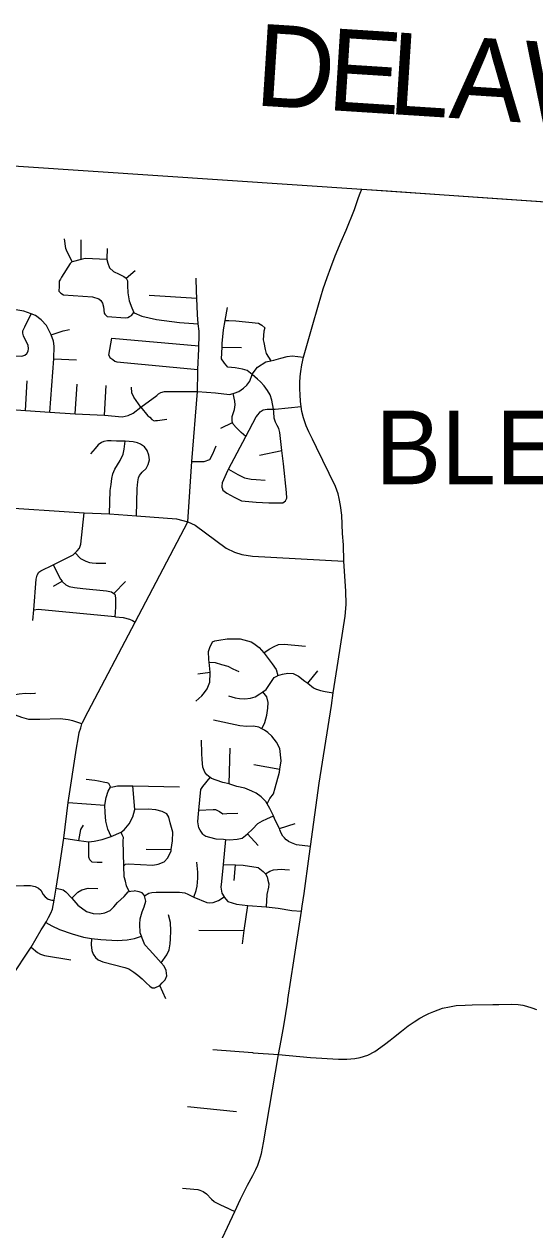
# Model space of a CAD drawing. Extents: x 1755200 to 1902939, y 644115 to 788070.
# Drawn here: x 1856712 to 1862951, y 763803 to 778525 of the extents above; entities that cross this region are included whole.
import ezdxf

# ---------------------------------------------------------------- set-up
doc = ezdxf.new("R2010")
doc.units = 0
for name, color, linetype in [('GM_X_Adjacent_County_Text', 7, 'Continuous'), ('GM_X_City_Street', 7, 'Continuous'), ('GM_X_County', 7, 'Continuous'), ('GM_X_County_Road', 7, 'Continuous'), ('GM_X_Township_Text', 7, 'Continuous')]:
    doc.layers.add(name, color=color, linetype=linetype)

msp = doc.modelspace()

# ---------------------------------------------------------------- linework, layer by layer
at = {"layer": 'GM_X_City_Street'}
for points in [[(1851193, 777116), (1851228, 777114), (1853977, 776957), (1854746, 776908), (1855849, 776844), (1860837, 776510)], [(1860818, 776461), (1860837, 776510)], [(1860837, 776510), (1861151, 776489)], [(1860586, 775869), (1860647, 776011), (1860746, 776261), (1860798, 776408), (1860818, 776461)], [(1857298, 775622), (1857229, 775764), (1857221, 775784), (1857207, 775903)], [(1857407, 775651), (1857408, 775893)], [(1857727, 775786), (1857721, 775660), (1857724, 775649), (1857736, 775608), (1857754, 775551), (1857803, 775506), (1857872, 775472), (1857929, 775444), (1857960, 775422), (1857973, 775391), (1857976, 775333), (1857977, 775243), (1857996, 775146), (1858028, 775061), (1858054, 775005), (1858058, 774998), (1858151, 774958), (1858331, 774917), (1858612, 774883), (1858840, 774864)], [(1860109, 767756), (1860133, 767908), (1860195, 768367), (1860210, 768482), (1860314, 769257), (1860465, 770206), (1860488, 770360), (1860547, 770745), (1860633, 771296), (1860638, 771339), (1860645, 771441), (1860641, 771603), (1860619, 771968), (1860612, 772166), (1860602, 772305), (1860591, 772531), (1860578, 772649), (1860562, 772731), (1860547, 772789), (1860515, 772880), (1860282, 773356), (1860233, 773457), (1860188, 773548), (1860159, 773620), (1860123, 773719), (1860103, 773796), (1860096, 773856), (1860089, 773919), (1860083, 774004), (1860080, 774068), (1860080, 774146), (1860084, 774222), (1860091, 774284), (1860106, 774366), (1860125, 774459), (1860230, 774829), (1860307, 775098), (1860364, 775294), (1860413, 775431), (1860457, 775554), (1860512, 775695), (1860586, 775869)], [(1857724, 775649), (1857456, 775664), (1857407, 775651), (1857298, 775622), (1857291, 775620), (1857274, 775601), (1857169, 775437), (1857155, 775410), (1857142, 775386), (1857140, 775320), (1857137, 775266), (1857162, 775239), (1857195, 775220), (1857548, 775195), (1857625, 775170), (1857651, 775150), (1857670, 775119), (1857681, 775075), (1857688, 774994), (1857698, 774984), (1857725, 774957), (1857952, 774937), (1857980, 774942), (1858001, 774954), (1858023, 774967), (1858054, 775005)], [(1857960, 775422), (1858067, 775517)], [(1857028, 773787), (1857074, 774437), (1857079, 774594), (1857071, 774655), (1857042, 774730), (1856987, 774846), (1856919, 774916), (1856851, 774967), (1856800, 774989), (1856708, 775020), (1856611, 775037), (1856360, 775047), (1856260, 775066), (1856193, 775100), (1856147, 775134), (1856103, 775185), (1856062, 775243), (1856028, 775301), (1855972, 775345), (1855924, 775367), (1855856, 775388), (1855762, 775403)], [(1858829, 774041), (1858834, 774276), (1858836, 774306), (1858845, 774560), (1858846, 774598), (1858851, 774706), (1858851, 774778), (1858840, 774864), (1858839, 774868), (1858828, 774977), (1858824, 775085), (1858822, 775171), (1858822, 775177), (1858819, 775266), (1858813, 775422)], [(1858238, 775216), (1858822, 775177)], [(1856147, 775134), (1856074, 775049), (1856060, 775012), (1856050, 774963), (1856032, 774679), (1856038, 774640), (1856054, 774605), (1856082, 774581), (1856138, 774549), (1856211, 774520), (1856307, 774497), (1856413, 774488), (1856605, 774476), (1856685, 774470), (1856721, 774482), (1856747, 774503), (1856763, 774531), (1856767, 774563), (1856762, 774602), (1856703, 774718), (1856695, 774751), (1856697, 774781), (1856720, 774827), (1856800, 774989)], [(1859497, 774248), (1859436, 774295), (1859379, 774313), (1859291, 774329), (1859200, 774338), (1859161, 774387), (1859123, 774440), (1859130, 774582), (1859132, 774624), (1859147, 774792), (1859168, 774907), (1859197, 775065)], [(1859168, 774907), (1859212, 774906), (1859300, 774904), (1859573, 774874), (1859614, 774849), (1859653, 774818), (1859642, 774778), (1859631, 774670), (1859642, 774636), (1859657, 774553), (1859670, 774503), (1859724, 774414)], [(1857042, 774730), (1857189, 774782), (1857267, 774796)], [(1857748, 774484), (1857785, 774691), (1858846, 774598)], [(1859130, 774582), (1859366, 774575)], [(1856507, 773824), (1856728, 773807), (1857028, 773787), (1857335, 773766), (1857694, 773749), (1857911, 773728), (1857984, 773747), (1858045, 773774), (1858139, 773846), (1858332, 773992), (1858353, 774012), (1858383, 774027), (1858427, 774038), (1858521, 774038), (1858829, 774041), (1859048, 774022), (1859221, 774004), (1859267, 774015), (1859277, 774017), (1859334, 774040), (1859390, 774080), (1859433, 774118), (1859468, 774165), (1859497, 774248), (1859498, 774252), (1859562, 774337), (1859666, 774401), (1859724, 774414), (1859764, 774423), (1859848, 774445), (1859927, 774465), (1859987, 774474), (1860125, 774459)], [(1857074, 774437), (1857350, 774427)], [(1857748, 774484), (1857759, 774456), (1857794, 774431), (1857821, 774410), (1857845, 774403), (1858836, 774306)], [(1856728, 773807), (1856749, 774169)], [(1857335, 773766), (1857359, 774129)], [(1859904, 772706), (1859921, 772736), (1859918, 772806), (1859882, 773158), (1859862, 773317), (1859835, 773537), (1859824, 773586), (1859802, 773626), (1859783, 773663), (1859768, 773713), (1859764, 773793), (1859758, 773825), (1859737, 773932), (1859717, 773997), (1859686, 774050), (1859645, 774107), (1859600, 774158), (1859563, 774191), (1859497, 774248)], [(1857694, 773749), (1857713, 774113)], [(1858139, 773846), (1858052, 773970), (1858028, 774025), (1858023, 774091)], [(1858712, 772446), (1858760, 773186), (1858829, 774041)], [(1859420, 773489), (1859365, 773540), (1859308, 773595), (1859267, 773640), (1859259, 773661), (1859252, 773681), (1859255, 773735), (1859283, 773818), (1859290, 773876), (1859287, 773921), (1859267, 774015)], [(1858139, 773846), (1858225, 773742), (1858248, 773724), (1858274, 773699), (1858299, 773681), (1858318, 773684), (1858340, 773684), (1858454, 773703)], [(1859130, 772862), (1859130, 772894), (1859137, 772912), (1859135, 772930), (1859202, 773075), (1859210, 773089), (1859420, 773489), (1859547, 773730), (1859569, 773760), (1859594, 773789), (1859631, 773815), (1859681, 773825), (1859758, 773825), (1859777, 773825), (1860096, 773856)], [(1859116, 773592), (1859259, 773661)], [(1858083, 772520), (1858093, 772856), (1858103, 772938), (1858111, 772987), (1858121, 773014), (1858154, 773053), (1858204, 773100), (1858228, 773149), (1858244, 773206), (1858236, 773261), (1858217, 773320), (1858182, 773364), (1858135, 773398), (1858097, 773413), (1858046, 773426), (1857946, 773431), (1857839, 773431), (1857777, 773435), (1857729, 773436), (1857687, 773428), (1857656, 773416), (1857618, 773389), (1857581, 773345), (1857521, 773278)], [(1857753, 772545), (1857765, 772829), (1857774, 772905), (1857783, 772977), (1857797, 773033), (1857821, 773092), (1857884, 773196), (1857922, 773274), (1857935, 773335), (1857946, 773431)], [(1858760, 773186), (1858911, 773183), (1858982, 773209), (1859019, 773280), (1859056, 773374)], [(1859588, 773263), (1859862, 773317)], [(1859210, 773089), (1859321, 773026), (1859406, 772984), (1859484, 772968), (1859548, 772963), (1859656, 772956)], [(1859130, 772862), (1859139, 772834), (1859190, 772797), (1859279, 772749), (1859366, 772705), (1859546, 772688), (1859700, 772679), (1859820, 772680), (1859872, 772679), (1859904, 772706)], [(1855772, 772483), (1856143, 772622), (1856193, 772633), (1856234, 772636), (1856339, 772631), (1857445, 772557), (1857753, 772545), (1858083, 772520), (1858575, 772486), (1858649, 772466), (1858712, 772446), (1858803, 772406), (1859181, 772127), (1859281, 772079), (1859372, 772050), (1859503, 772030), (1860619, 771968)], [(1856820, 771244), (1856830, 771374), (1856858, 771748), (1856873, 771796), (1856893, 771832), (1856915, 771848), (1857067, 771924), (1857310, 772047), (1857337, 772068), (1857360, 772093), (1857387, 772126), (1857403, 772174), (1857445, 772557)], [(1856549, 766881), (1856798, 767255), (1856921, 767465), (1856954, 767517), (1856979, 767556), (1856986, 767567), (1857010, 767617), (1857039, 767669), (1857057, 767719), (1857078, 767829), (1857103, 767973), (1857141, 768207), (1857198, 768584), (1857249, 769022), (1857351, 769683), (1857372, 769799), (1857386, 769877), (1857403, 769931), (1857419, 769983), (1857427, 769997), (1857496, 770133), (1858068, 771223), (1858712, 772446)], [(1857337, 772068), (1857402, 772002), (1857464, 771967), (1857511, 771951), (1857543, 771949), (1857591, 771942), (1857711, 771943)], [(1857067, 771924), (1857155, 771749), (1857176, 771722), (1857182, 771714), (1857223, 771677), (1857261, 771659), (1857327, 771647), (1857428, 771633), (1857720, 771606), (1857778, 771593), (1857807, 771574), (1857819, 771566), (1857828, 771519), (1857830, 771425), (1857824, 771327), (1857819, 771305), (1857819, 771291)], [(1857071, 771663), (1857176, 771722)], [(1857807, 771574), (1857952, 771719)], [(1856830, 771374), (1856884, 771381), (1857097, 771361), (1857819, 771291), (1857830, 771289), (1857922, 771278), (1857998, 771261), (1858036, 771243), (1858068, 771223)], [(1858808, 770257), (1858881, 770324), (1858917, 770364), (1858950, 770408), (1858981, 770492), (1858984, 770602), (1858983, 770613), (1858971, 770736), (1858968, 770768), (1858963, 770864), (1858980, 770912), (1859015, 770984)], [(1859015, 770984), (1859041, 770994), (1859089, 771005), (1859191, 771020), (1859353, 771018), (1859487, 770982), (1859518, 770964), (1859582, 770915), (1859640, 770849), (1859643, 770846), (1859741, 770716), (1859791, 770646), (1859813, 770571)], [(1859640, 770849), (1859706, 770895), (1859768, 770924), (1859818, 770950), (1859888, 770955), (1860150, 770928)], [(1858971, 770736), (1859046, 770731), (1859125, 770704), (1859199, 770685), (1859261, 770654), (1859334, 770619)], [(1858832, 770590), (1858983, 770613)], [(1859209, 770322), (1859288, 770297), (1859344, 770289), (1859408, 770288), (1859476, 770295), (1859533, 770312), (1859593, 770346), (1859628, 770371), (1859670, 770401), (1859716, 770474), (1859767, 770548), (1859808, 770569), (1859813, 770571), (1859868, 770587), (1859934, 770600), (1859998, 770596), (1860062, 770564), (1860140, 770504), (1860177, 770476), (1860245, 770422), (1860279, 770404), (1860283, 770403)], [(1860177, 770476), (1860299, 770629)], [(1857419, 769983), (1857309, 770018), (1857251, 770032), (1857151, 770042), (1856903, 770035), (1856771, 770034), (1856685, 770059), (1856606, 770086), (1856548, 770111), (1856518, 770156), (1856476, 770198), (1856447, 770247), (1856426, 770319), (1856417, 770395), (1856427, 770499)], [(1856426, 770319), (1856497, 770346), (1856579, 770337), (1856653, 770348), (1856727, 770355), (1856791, 770353), (1856845, 770356), (1856851, 770356)], [(1859615, 769922), (1859651, 769998), (1859676, 770086), (1859687, 770172), (1859694, 770240), (1859675, 770312), (1859628, 770371)], [(1860283, 770403), (1860333, 770388), (1860388, 770377), (1860488, 770360)], [(1859680, 769006), (1859714, 769069), (1859760, 769127), (1859779, 769201), (1859832, 769393), (1859837, 769429), (1859853, 769531), (1859834, 769680), (1859796, 769758), (1859737, 769829), (1859687, 769875), (1859647, 769906), (1859615, 769922), (1859578, 769940), (1859512, 769951), (1859432, 769948), (1859348, 769956), (1859026, 770025)], [(1859913, 768567), (1859892, 768588), (1859874, 768610), (1859851, 768647), (1859834, 768686), (1859830, 768705), (1859776, 768814), (1859758, 768858), (1859752, 768873), (1859713, 768947), (1859680, 769006), (1859665, 769032), (1859608, 769092), (1859548, 769133), (1859492, 769161), (1859410, 769196), (1859312, 769217), (1859225, 769246), (1859217, 769247), (1859139, 769264), (1859057, 769293), (1858999, 769315), (1858983, 769328), (1858943, 769358), (1858919, 769392), (1858896, 769454), (1858885, 769545), (1858883, 769619), (1858880, 769783)], [(1859217, 769247), (1859227, 769685)], [(1859520, 769483), (1859837, 769429)], [(1857472, 769307), (1857576, 769294), (1857620, 769286), (1857700, 769269), (1857722, 769265), (1857742, 769255), (1857768, 769210)], [(1858894, 768635), (1858863, 768685), (1858847, 768713), (1858833, 768783), (1858838, 768838), (1858846, 768929), (1858870, 769180), (1858896, 769218), (1858983, 769328)], [(1857198, 768584), (1857382, 768558), (1857504, 768540), (1857567, 768549), (1857667, 768568), (1857774, 768605), (1857896, 768660), (1857934, 768686), (1857995, 768760), (1858041, 768844), (1858066, 768935), (1858038, 769224)], [(1857774, 768605), (1857736, 768696), (1857711, 768792), (1857702, 768900), (1857698, 768988), (1857713, 769081), (1857739, 769161), (1857768, 769210), (1857794, 769214), (1857852, 769226), (1858038, 769224)], [(1858038, 769224), (1858608, 769214)], [(1857249, 769022), (1857698, 768988)], [(1857930, 768249), (1857949, 768267), (1857983, 768273), (1858283, 768256), (1858351, 768268), (1858424, 768295), (1858466, 768347), (1858507, 768429), (1858510, 768449), (1858526, 768553), (1858528, 768658), (1858497, 768772), (1858481, 768840), (1858456, 768883), (1858400, 768911), (1858322, 768930), (1858228, 768940), (1858066, 768935)], [(1858846, 768929), (1859022, 768934), (1859048, 768936), (1859098, 768911), (1859141, 768884), (1859187, 768886), (1859323, 768892)], [(1858894, 768635), (1858932, 768610), (1858976, 768598), (1859052, 768577), (1859146, 768575), (1859171, 768571), (1859220, 768564), (1859316, 768575), (1859376, 768587), (1859416, 768619), (1859439, 768640), (1859501, 768696), (1859565, 768764), (1859622, 768798), (1859676, 768821), (1859758, 768858)], [(1857382, 768558), (1857404, 768691), (1857436, 768745)], [(1859830, 768705), (1860021, 768764)], [(1857665, 768288), (1857604, 768288), (1857545, 768292), (1857516, 768321), (1857504, 768353), (1857504, 768464), (1857504, 768540)], [(1857996, 767934), (1857962, 768004), (1857950, 768061), (1857934, 768115), (1857930, 768249), (1857921, 768554), (1857926, 768592), (1857910, 768626), (1857896, 768660)], [(1859171, 768571), (1859142, 768264), (1859122, 768056), (1859116, 767986), (1859127, 767913), (1859155, 767868), (1859157, 767865), (1859201, 767811), (1859255, 767794), (1859307, 767778), (1859445, 767765), (1859669, 767748), (1859817, 767731), (1859981, 767704), (1860099, 767693)], [(1859439, 768640), (1859570, 768494)], [(1860210, 768482), (1860039, 768506), (1859979, 768529), (1859943, 768546), (1859915, 768566), (1859913, 768567)], [(1858203, 768450), (1858510, 768449)], [(1858785, 767866), (1858812, 767947), (1858826, 767999), (1858836, 768099), (1858835, 768171), (1858820, 768291)], [(1859142, 768264), (1859294, 768259), (1859388, 768256), (1859571, 768226), (1859633, 768179), (1859662, 768148), (1859680, 768112), (1859691, 768073), (1859700, 768026), (1859698, 767988), (1859675, 767897), (1859669, 767748)], [(1859277, 768067), (1859294, 768259)], [(1859662, 768148), (1859714, 768184), (1859760, 768200), (1859806, 768204), (1859852, 768205), (1859895, 768201), (1859952, 768199)], [(1856604, 768002), (1856707, 768008), (1856791, 768006), (1856849, 767996), (1856887, 767976), (1856917, 767949), (1856945, 767899), (1856969, 767868), (1857005, 767841), (1857051, 767830), (1857078, 767829)], [(1857103, 767973), (1857191, 767955), (1857223, 767930), (1857294, 767854), (1857370, 767766), (1857475, 767689), (1857557, 767664), (1857632, 767660), (1857696, 767675), (1857762, 767704), (1857808, 767745), (1857854, 767801), (1857935, 767874), (1857981, 767930), (1857996, 767934), (1858015, 767940), (1858057, 767942)], [(1857294, 767854), (1857369, 767926), (1857419, 767956), (1857495, 767975), (1857614, 767969)], [(1858369, 766785), (1858400, 766818), (1858434, 766856), (1858454, 766904), (1858449, 766968), (1858421, 767023), (1858385, 767065), (1858353, 767101), (1858248, 767216), (1858187, 767281), (1858153, 767363), (1858144, 767388), (1858128, 767430), (1858124, 767534), (1858131, 767602), (1858155, 767686), (1858180, 767748), (1858198, 767818), (1858189, 767848), (1858182, 767882), (1858181, 767886), (1858153, 767917), (1858117, 767929), (1858057, 767942)], [(1858182, 767882), (1858235, 767912), (1858274, 767924), (1858324, 767927), (1858610, 767925), (1858677, 767917), (1858713, 767900), (1858767, 767873), (1858785, 767866), (1858944, 767801), (1858976, 767795), (1859022, 767800), (1859088, 767823), (1859155, 767868)], [(1858385, 767065), (1858454, 767161), (1858482, 767221), (1858497, 767295), (1858501, 767355), (1858504, 767453), (1858501, 767557), (1858475, 767650)], [(1859378, 767295), (1859401, 767457), (1859445, 767765)], [(1859935, 766614), (1860006, 767088), (1860099, 767693), (1860109, 767756)], [(1856979, 767556), (1857050, 767516), (1857143, 767471), (1857299, 767416), (1857439, 767375), (1857535, 767362), (1857651, 767347), (1857849, 767334), (1857969, 767345), (1858061, 767362), (1858144, 767388)], [(1857535, 767362), (1857530, 767282), (1857538, 767214), (1857556, 767170), (1857583, 767127), (1857617, 767099), (1857673, 767076), (1857941, 767006), (1857991, 766988), (1858054, 766949), (1858100, 766911), (1858154, 766866), (1858203, 766820), (1858247, 766778), (1858275, 766759), (1858307, 766759), (1858369, 766785)], [(1858846, 767464), (1859401, 767457)], [(1856798, 767255), (1856875, 767189), (1856913, 767170), (1856963, 767152), (1857281, 767098)], [(1858444, 766624), (1858369, 766785)], [(1858415, 761892), (1858540, 762228), (1858822, 762982), (1858965, 763341), (1859046, 763516), (1859284, 764028), (1859356, 764179), (1859439, 764347), (1859505, 764468), (1859543, 764541), (1859567, 764591), (1859589, 764654), (1859613, 764735), (1859638, 764867), (1859818, 765942), (1859852, 766114), (1859884, 766295), (1859932, 766596), (1859935, 766614)], [(1859818, 765942), (1860212, 765909), (1860552, 765886), (1860654, 765886), (1860753, 765895), (1860816, 765906), (1860912, 765935), (1860996, 765981), (1861116, 766067), (1861184, 766121), (1861223, 766152)], [(1859019, 766007), (1859503, 765967), (1859511, 765966)], [(1859511, 765966), (1859818, 765942)], [(1858708, 765308), (1859308, 765249)], [(1858647, 764313), (1858786, 764300), (1858833, 764295), (1858859, 764289), (1858898, 764272), (1858941, 764244), (1858999, 764179), (1859035, 764148)], [(1859035, 764148), (1859037, 764147), (1859087, 764121), (1859181, 764075), (1859184, 764074)], [(1859184, 764074), (1859224, 764054), (1859284, 764028)]]:
    msp.add_lwpolyline(points, dxfattribs=at)
at = {"layer": 'GM_X_County'}
msp.add_lwpolyline([(1843361, 777564), (1845449, 777453), (1847560, 777333), (1848085, 777300), (1848276, 777289), (1848580, 777271), (1850569, 777151), (1850744, 777141), (1850903, 777132), (1851193, 777116), (1851228, 777114), (1853977, 776957), (1854746, 776908), (1855849, 776844), (1860837, 776510), (1864331, 776270)], dxfattribs=at)
at = {"layer": 'GM_X_County_Road'}
for points in [[(1861151, 776489), (1861727, 776449)], [(1861727, 776449), (1862250, 776413)], [(1862250, 776413), (1864029, 776290)], [(1861223, 766152), (1861321, 766230), (1861403, 766292), (1861477, 766344), (1861544, 766387), (1861613, 766423), (1861657, 766446), (1861718, 766471), (1861823, 766508), (1861907, 766528), (1861991, 766542), (1862100, 766548), (1862186, 766552), (1862439, 766555)], [(1862439, 766555), (1862510, 766556), (1862668, 766560), (1862748, 766554), (1862803, 766545), (1862850, 766533), (1862913, 766515), (1862969, 766494)]]:
    msp.add_lwpolyline(points, dxfattribs=at)

# ---------------------------------------------------------------- texts
at = {"layer": 'GM_X_Adjacent_County_Text'}
for s, rotation, p in [('D', 356.3406, (1859516, 777534)), ('E', 356.3415, (1860399, 777478)), ('L', 356.3411, (1861146, 777430)), ('A', 356.3406, (1861892, 777382)), ('W', 356.3413, (1862775, 777326))]:
    msp.add_text(s, height=1000, rotation=rotation, dxfattribs=at).set_placement(p)
at = {"layer": 'GM_X_Township_Text'}
msp.add_text('BLENDON', height=900, rotation=0, dxfattribs=at).set_placement((1861003, 772907))

doc.saveas('drawing.dxf')
